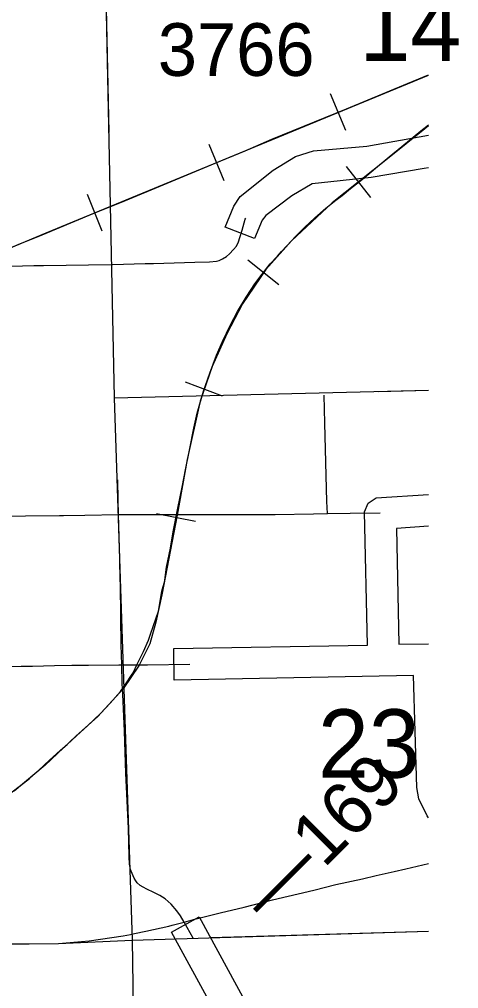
# Model space of a CAD drawing. Extents: x 10133 to 81668, y 5524 to 11018.
# Drawn here: x 15848.7 to 15952.9, y 8429.5 to 8659.6 of the extents above; entities that cross this region are included whole.
import ezdxf

# ---------------------------------------------------------------- set-up
doc = ezdxf.new("R2010")
doc.units = 0
doc.layers.add('Default', color=7, linetype='Continuous')
doc.layers.add('trf_Signal_(Temp)_Layout', color=7, linetype='Continuous')

msp = doc.modelspace()

# ---------------------------------------------------------------- linework, layer by layer
at = {"layer": 'Default'}
for p, q in [((15926.08, 8633.25), (15922.51, 8641.92)), ((15897.22, 8621.24), (15893.67, 8629.92)), ((15932.05, 8617.28), (15926.29, 8624.68)), ((15868.3, 8609.33), (15864.8, 8618.02)), ((15910.24, 8596.61), (15902.9, 8602.44)), ((15896.87, 8570.18), (15888.08, 8573.45)), ((15890.42, 8540.41), (15881.21, 8542.19))]:
    msp.add_line(p, q, dxfattribs=at)
for points in [[(15868.57, 8695.4), (15871.16, 8569.73)], [(15868.94, 8677.06), (15869.86, 8632.7)], [(15634.57, 8583.48), (15680.46, 8567.12), (15704.09, 8558.72), (15709.61, 8557.17), (15714.13, 8556.32), (15720.37, 8556.06), (15725.61, 8556.46), (15732.39, 8558.11), (15745.37, 8562.36), (15750.97, 8564.86), (15777.57, 8576.8), (15786.75, 8580.67), (15816.48, 8592.77), (15828.44, 8597.89), (15841.17, 8603.13), (15855, 8608.89), (15945.75, 8646.38)], [(15779.83, 8578.06), (15783.1, 8579.42), (15786.86, 8580.98), (15788.74, 8581.74), (15792.27, 8583.16), (15805.17, 8588.31), (15807.94, 8589.44), (15815.27, 8592.49), (15826.07, 8596.98), (15831.55, 8599.23), (15844.26, 8604.45), (15848.37, 8606.16), (15854.05, 8608.48), (15866.13, 8613.51), (15873.82, 8616.6), (15881.82, 8619.95), (15895.1, 8625.44), (15902.22, 8628.36), (15908.58, 8631.12), (15926.26, 8638.39), (15940.77, 8644.38), (15945.75, 8646.44)], [(15779.83, 8578.06), (15783.1, 8579.42), (15786.86, 8580.98), (15788.74, 8581.74), (15792.27, 8583.16), (15805.17, 8588.31), (15807.94, 8589.44), (15815.27, 8592.49), (15826.07, 8596.98), (15831.55, 8599.23), (15844.26, 8604.45), (15848.37, 8606.16), (15854.05, 8608.48), (15866.13, 8613.51), (15873.82, 8616.6), (15881.82, 8619.95), (15895.1, 8625.44), (15902.22, 8628.36), (15908.58, 8631.12), (15926.26, 8638.39), (15940.77, 8644.38), (15945.75, 8646.44)], [(15846.66, 8475.98), (15848.92, 8477.73), (15851.03, 8479.4), (15853.22, 8481.34), (15855.83, 8483.74), (15858.42, 8486.15), (15859.99, 8487.49), (15862.24, 8489.55), (15864.94, 8492.02), (15867.9, 8494.86), (15870.17, 8497.29), (15872.66, 8500.04), (15874.09, 8502.14), (15875.27, 8503.9), (15875.69, 8504.52), (15876.61, 8506.56), (15878.09, 8509.52), (15879.3, 8512.25), (15879.78, 8513.7), (15881.65, 8519.16), (15882.46, 8523.9), (15883.14, 8526.29), (15883.2, 8526.51), (15883.6, 8529.58), (15884.5, 8534.11), (15885.17, 8537.95), (15886.25, 8543.57), (15887.39, 8548.98), (15888.08, 8552.65), (15889.03, 8557.3), (15890.09, 8562.57), (15890.83, 8566.13), (15892.31, 8571.38), (15893.88, 8575.61), (15895.41, 8579.91), (15896.82, 8583.17), (15898.74, 8587.1), (15900.38, 8590.22), (15902.5, 8593.68), (15904.49, 8596.8), (15906.23, 8599.09), (15908.17, 8601.54), (15909.92, 8603.42), (15910.87, 8604.5), (15912.1, 8605.84), (15914.2, 8608.04), (15916.42, 8610.28), (15918.8, 8612.45), (15921.37, 8614.74), (15923.75, 8616.68), (15925.23, 8617.79), (15927.24, 8619.48), (15930.04, 8621.65), (15933.18, 8624.27), (15936.37, 8626.95), (15939.4, 8629.44), (15943.91, 8633.1), (15945.75, 8634.55)], [(15945.75, 8634.29), (15944.89, 8633.6), (15936.03, 8626.52), (15922.88, 8616.05), (15913.19, 8607.05), (15907.12, 8600.24), (15901.6, 8592.11), (15897.91, 8584.99), (15894.42, 8577.16), (15891.54, 8568.96), (15888.5, 8555.13), (15886.11, 8541.91), (15882.44, 8522.97), (15881.03, 8516.52), (15879.63, 8511.38), (15877.11, 8506.3), (15873.25, 8500.7), (15867.3, 8494.14), (15862.06, 8489.43), (15854.8, 8482.61), (15847.4, 8476.39)], [(15945.75, 8624.35), (15944.69, 8624.17), (15932.15, 8622.09), (15918.12, 8620.55), (15913.27, 8617.71), (15907.17, 8613.02), (15906.29, 8611.96), (15904.47, 8607.54), (15897.49, 8610.28), (15899.57, 8615.28), (15901.08, 8617.52), (15908.86, 8623.78), (15914.18, 8627.07), (15918.41, 8628.37), (15931.08, 8629.51), (15945.75, 8632.1)], [(15846.7, 8601.03), (15852.12, 8601.15), (15854.42, 8601.19), (15870.43, 8601.43), (15870.79, 8601.44), (15878.52, 8601.63), (15880.45, 8601.68), (15890.27, 8601.97), (15893.76, 8602.08), (15895.43, 8602.23), (15896.08, 8602.39), (15896.85, 8602.76), (15897.8, 8603.31), (15898.51, 8603.96), (15899.5, 8604.98), (15900.15, 8605.78), (15900.64, 8606.82), (15900.98, 8607.78), (15901.5, 8609.54), (15902.24, 8612.13), (15902.35, 8612.4)], [(15871.16, 8569.73), (15945.75, 8571.56)], [(15871.16, 8569.73), (15875.44, 8441.06)], [(15921.8, 8542.3), (15921.62, 8545.15), (15921.13, 8563.77), (15921, 8570.4)], [(15933.82, 8571.27), (15945.75, 8571.56)], [(15872.19, 8542.03), (15872.09, 8545.45), (15872.01, 8550.26)], [(15945.75, 8470.04), (15945.4, 8470.52), (15943.43, 8474.57), (15942.98, 8477.3), (15942.21, 8503.86), (15885.4, 8502.73), (15885.28, 8510.23), (15931.22, 8511.03), (15930.56, 8542.67), (15931.39, 8544.79), (15933.29, 8546.04), (15945.75, 8546.83)], [(15836.71, 8541.59), (15844.35, 8541.67), (15850.1, 8541.73), (15858.21, 8541.81), (15858.21, 8541.81), (15859.12, 8541.82), (15864.18, 8541.9), (15872.19, 8542.03)], [(15872.19, 8542.03), (15874.29, 8542.07), (15885.68, 8542.05), (15892.78, 8542.04), (15902.61, 8542.07), (15909.34, 8542.1), (15918.46, 8542.25), (15921.8, 8542.3), (15927.15, 8542.38), (15934.3, 8542.43)], [(15872.96, 8506.4), (15872.83, 8511.11), (15872.73, 8517.64), (15872.62, 8525.95), (15872.61, 8526.18), (15872.49, 8531.67), (15872.42, 8534.08), (15872.19, 8542.03)], [(15945.75, 8539.27), (15938.13, 8538.74), (15938.71, 8511.26), (15945.75, 8511.4)], [(15781.61, 8504.88), (15786.19, 8504.95), (15789.88, 8505.03), (15794.73, 8505.14), (15797.89, 8505.18), (15809.99, 8505.36), (15811.23, 8505.38), (15819.05, 8505.54), (15823.8, 8505.63), (15826.56, 8505.68), (15833.83, 8505.79), (15839.37, 8505.88), (15841.83, 8505.92), (15849.09, 8506.05), (15851.79, 8506.09), (15856.96, 8506.2), (15861.07, 8506.28), (15863.99, 8506.31), (15865.07, 8506.32), (15872.23, 8506.4), (15872.96, 8506.4)], [(15872.96, 8506.4), (15879.04, 8506.37), (15889.09, 8506.54)], [(15889.89, 8441.5), (15887.74, 8445.33), (15886.92, 8446.8), (15886.02, 8448), (15884.67, 8449.55), (15883.25, 8450.81), (15881.95, 8451.61), (15880.53, 8452.38), (15878.93, 8453.15), (15878.04, 8453.58), (15877.3, 8454.02), (15876.62, 8454.66), (15876.31, 8455.09), (15875.88, 8455.77), (15875.39, 8456.85), (15875.05, 8457.84), (15874.8, 8459.07), (15874.74, 8460.86), (15874.52, 8467.52), (15873.94, 8480.68), (15873.57, 8490.61), (15873.18, 8499.42), (15873.07, 8501.95), (15872.96, 8506.4)], [(15945.75, 8370.32), (15903.11, 8411.94), (15898.16, 8418.3), (15884.79, 8442.93), (15891.33, 8446.6), (15904.63, 8422.1), (15908.72, 8416.91), (15945.75, 8380.79)], [(15875.44, 8441.06), (15945.75, 8443.2)], [(15894.12, 8441.63), (15945.75, 8443.2)], [(15749.8, 8439.6), (15857.91, 8440.25), (15875.44, 8441.06)], [(15875.44, 8441.06), (15877.27, 8318.69)], [(15875.44, 8441.06), (15877.27, 8318.69)]]:
    msp.add_lwpolyline(points, dxfattribs=at)
at = {"layer": 'trf_Signal_(Temp)_Layout'}
msp.add_lwpolyline([(15843.91, 8440.1), (15857.91, 8440.25), (15865.19, 8440.89), (15867.9, 8441.24), (15870.6, 8441.64), (15873.3, 8442.09), (15875, 8442.41), (15875.98, 8442.59), (15878.66, 8443.14), (15884.09, 8444.38), (15884.92, 8444.59), (15887.75, 8445.33), (15889.41, 8445.77), (15890.29, 8445.99), (15896.26, 8447.52), (15902, 8448.85), (15908.75, 8450.57), (15918.49, 8452.88), (15923.76, 8454.21), (15930.05, 8455.63), (15933.31, 8456.37), (15937.62, 8457.36), (15940.37, 8458), (15945.75, 8459.27)], dxfattribs=at)

# ---------------------------------------------------------------- texts
at = {"layer": 'Default'}
for s, height, rotation, p in [('14', 16.25, 0.0291, (15929.34, 8649.73)), ('23', 16.25, 0.0291, (15919.5, 8479.57)), ('‒‒169', 12.5, 45, (15907.78, 8444.78))]:
    msp.add_text(s, height=height, rotation=rotation, dxfattribs=at).set_placement(p)
msp.add_text('3766', height=12.5, dxfattribs=at).set_placement((15881.51, 8646.18))

doc.saveas('drawing.dxf')
